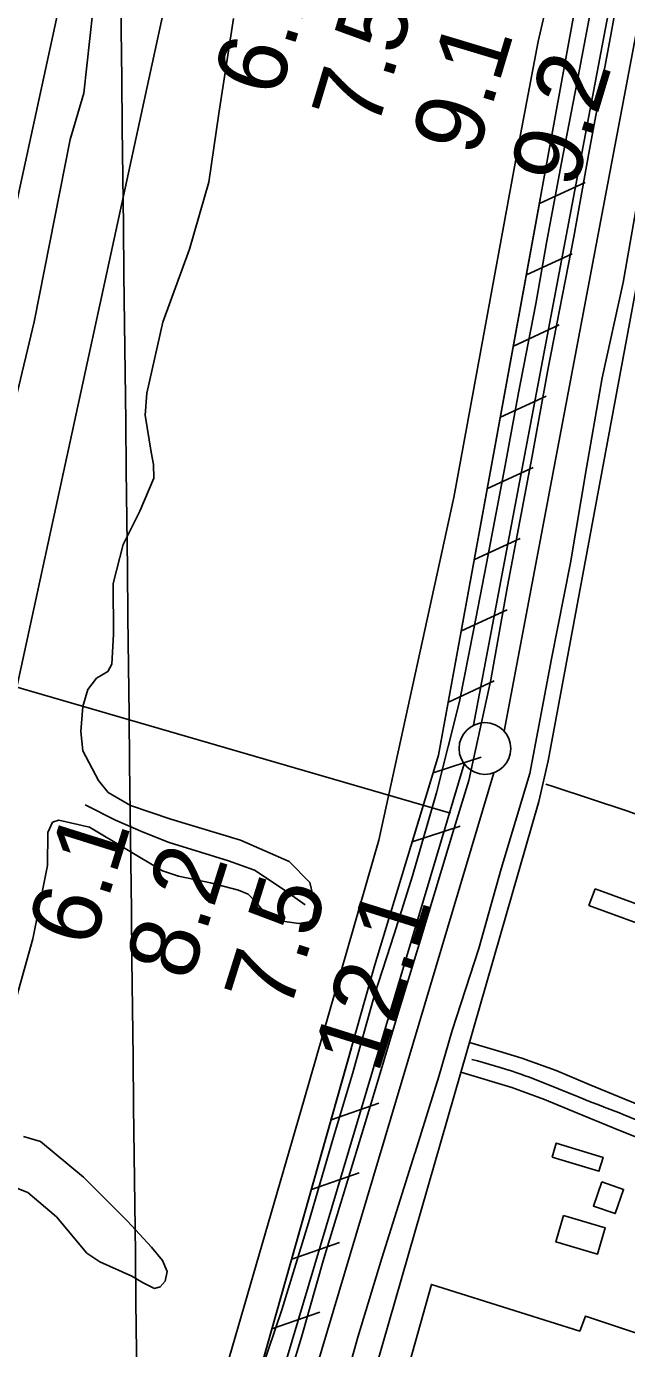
# Model space of a CAD drawing. Extents: x 3683613 to 3738215, y 469626 to 495384.
# Drawn here: x 3703578 to 3704159, y 477641 to 478919 of the extents above; entities that cross this region are included whole.
import ezdxf

# ---------------------------------------------------------------- set-up
doc = ezdxf.new("R2010")
doc.units = 0
for name, color, linetype in [('V-BLDG-OTLN', 7, 'Continuous'), ('V-DTCH-CNTR', 7, 'Continuous'), ('V-FLOD-BASE', 7, 'Continuous'), ('V-GRID-MAJR', 7, 'Continuous'), ('V-LEVE-TOET', 7, 'Continuous'), ('V-RIVR-EDGE', 7, 'Continuous'), ('V-RIVR-RANG', 7, 'Continuous'), ('V-ROAD-CNTR', 7, 'Continuous'), ('V-RRAP-FSHR', 7, 'Continuous'), ('V-SITE-VEGE', 7, 'Continuous'), ('V-SURV-LINE', 7, 'Continuous'), ('V-TOPO-DPTH', 7, 'Continuous'), ('V-TOPO-MINR', 7, 'Continuous'), ('V-TOPO-SHOR', 7, 'Continuous'), ('V-TOPO-WATR', 7, 'Continuous'), ('V-UTIL-LINE', 7, 'Continuous')]:
    doc.layers.add(name, color=color, linetype=linetype)

msp = doc.modelspace()

# ---------------------------------------------------------------- linework, layer by layer
at = {"layer": 'V-BLDG-OTLN'}
for points in [[(3704128.036, 478085.16000000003), (3704198.686, 478059.238), (3704192.823, 478043.25200000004), (3704122.171, 478069.173)], [(3704086.46, 477825.748), (3704090.546, 477839.179), (3704135.8310000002, 477825.4), (3704131.745, 477811.971)], [(3704134.612, 477801.68200000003), (3704155.713, 477794.393), (3704147.666, 477771.107), (3704126.568, 477778.396)], [(3704097.531, 477769.104), (3704137.957, 477757.433), (3704130.598, 477731.943), (3704090.173, 477743.615)]]:
    msp.add_lwpolyline(points, close=True, dxfattribs=at)
at = {"layer": 'V-DTCH-CNTR'}
for points in [[(3704299.161, 478107.469), (3704284.45, 478114.411), (3704159.711, 478160.291), (3704088.649, 478183.873), (3704080.5470000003, 478186.231)], [(3703940.634, 477598.05700000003), (3703969.83, 477702.53), (3704113.213, 477657.507), (3704118.744, 477671.767), (3704256.286, 477626.183)]]:
    msp.add_lwpolyline(points, dxfattribs=at)
at = {"layer": 'V-FLOD-BASE'}
msp.add_lwpolyline([(3704179.48, 479105.43700000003), (3704158.007, 478991.054), (3704143.785, 478912.54000000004), (3704122.216, 478796.748), (3704107.409, 478715.788), (3704082.765, 478588.667), (3704067.159, 478503.466), (3704043.253, 478377.768), (3704027.379, 478287.443), (3704005.91, 478189.825), (3703991.848, 478143.821), (3703959.222, 478035.969), (3703936.941, 477962.902), (3703911.352, 477877.732), (3703884.566, 477788.954), (3703865.73, 477727.612), (3703844.157, 477651.621), (3703814.27, 477552.788)], dxfattribs=at)
at = {"layer": 'V-GRID-MAJR'}
msp.add_spline([(3703712.5700000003, 475224.829), (3703642.089, 481281.841), (3703571.5670000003, 487342.321), (3703501.045, 493402.81200000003), (3703501.005, 493406.26900000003)], degree=3, dxfattribs=at)
at = {"layer": 'V-LEVE-TOET'}
for points in [[(3704167.595, 479178.552), (3704155.1350000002, 479106.82300000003), (3704142.522, 479036.837), (3704127.704, 478956.211), (3704110.899, 478865.651), (3704095.365, 478785.822), (3704081.258, 478709.867)], [(3704173.131, 478772.83900000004), (3704155.404, 478671.666), (3704135.034, 478579.27900000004), (3704119.889, 478492.476), (3704104.396, 478400.548), (3704085.899, 478307.737), (3704064.901, 478196.716), (3704037.193, 478104.628), (3704015.665, 478027.457), (3703989.876, 477948.212)], [(3704081.258, 478709.867), (3704070.838, 478650.867), (3704053.931, 478564.84), (3704041.09, 478494.5), (3704022.98, 478399.952), (3704010.366, 478335.085), (3703996.79, 478266.473), (3703974.703, 478178.004), (3703951.38, 478097.882), (3703933.81, 478041.16500000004), (3703915.095, 477983.608), (3703893.344, 477906.083), (3703874.94, 477845.042), (3703850.7490000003, 477762.108), (3703825.074, 477677.981), (3703798.679, 477599.884), (3703771.105, 477506.985), (3703750.997, 477439.04000000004), (3703724.04, 477344.642), (3703697.213, 477249.664), (3703669.512, 477152.107), (3703639.728, 477038.56), (3703627.069, 476980.907), (3703612.356, 476921.78500000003)], [(3703989.876, 477948.212), (3703976.92, 477903.701), (3703954.028, 477830.223), (3703953.694, 477829.516), (3703921.661, 477728.021), (3703898.488, 477651.512), (3703875.35, 477568.37), (3703845.859, 477462.511), (3703816.904, 477368.88), (3703788.816, 477278.18), (3703756.386, 477168.53), (3703730.927, 477064.506), (3703713.058, 476984.974), (3703701.682, 476943.381)]]:
    msp.add_lwpolyline(points, dxfattribs=at)
at = {"layer": 'V-RIVR-EDGE'}
msp.add_lwpolyline([(3703321.3665150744, 477624.2934469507), (3703330.4411275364, 477652.48635977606), (3703338.318062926, 477681.8828873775), (3703363.724602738, 477759.8625265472), (3703401.8700386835, 477891.23973639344), (3703437.577072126, 478007.6148098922), (3703453.9980650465, 478093.4209139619), (3703484.288831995, 478204.40644063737), (3703511.560171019, 478308.1955138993), (3703538.2549378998, 478421.59123897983), (3703567.407404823, 478557.7932989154), (3703585.6041313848, 478633.389459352), (3703620.258961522, 478809.7997979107), (3703633.577398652, 478854.7913626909), (3703642.1778643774, 478934.01321171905), (3703659.1576163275, 479003.00878842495), (3703684.6650971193, 479121.8103890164), (3703704.16192616, 479237.62521906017), (3703733.9295603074, 479379.82902418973), (3703760.087834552, 479519.04012106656), (3703797.7799057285, 479709.85078858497), (3703822.0793184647, 479825.6537432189)], dxfattribs=at)
at = {"layer": 'V-ROAD-CNTR'}
for points in [[(3703726.55050797, 476963.34804728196), (3703726.55050797, 476963.34804728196), (3704073.5738139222, 478169.58763479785), (3704082.870795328, 478208.9135561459), (3704324.341312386, 479507.44095908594), (3704404.9751511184, 479907.30515935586), (3704509.589941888, 480585.20680355)], [(3704006.546947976, 477936.6061007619), (3704034.9398911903, 477928.1241177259), (3704057.092846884, 477921.50713096), (3704090.301780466, 477909.30715536), (3704122.4497161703, 477895.78318240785), (3704157.01964703, 477881.80221036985), (3704191.8445773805, 477867.6362387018), (3704211.50453806, 477859.0012559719), (3704232.220496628, 477854.7082645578), (3704255.771449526, 477848.5402768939), (3704283.152394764, 477833.49030699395), (3704308.905343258, 477819.33533530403)], [(3703998.2529645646, 477907.776158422), (3704047.616865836, 477893.0271879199), (3704079.307802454, 477881.38521120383), (3704111.00973905, 477868.04923787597), (3704145.7436695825, 477854.00226597), (3704180.158600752, 477840.00229396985), (3704202.328556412, 477830.2653134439), (3704225.372510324, 477825.490322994), (3704244.5774719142, 477820.46033305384), (3704268.7024236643, 477807.2003595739), (3704294.455372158, 477793.0453878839)]]:
    msp.add_lwpolyline(points, dxfattribs=at)
msp.add_spline([(3704008.9379431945, 477920.2371334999), (3704052.3548563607, 477907.2671594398), (3704116.72972761, 477881.9162101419), (3704186.001589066, 477853.819266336), (3704206.916547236, 477844.633284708), (3704250.1744607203, 477834.50030497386), (3704301.680357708, 477806.19036159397)], degree=3, dxfattribs=at)
at = {"layer": 'V-RRAP-FSHR'}
for p, q in [((3704074.18, 478747.86600000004), (3704118.56, 478768.234)), ((3704061.6070000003, 478679.005), (3704105.987, 478699.373)), ((3704049.034, 478610.143), (3704093.414, 478630.511)), ((3704036.461, 478541.282), (3704080.841, 478561.65)), ((3704023.8880000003, 478472.42), (3704068.268, 478492.788)), ((3704011.315, 478403.558), (3704055.6950000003, 478423.92600000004)), ((3703998.742, 478334.697), (3704043.122, 478355.065)), ((3703986.169, 478265.835), (3704030.549, 478286.20300000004)), ((3703971.633, 478197.45), (3704018.051, 478212.609)), ((3703951.268, 478130.478), (3703997.686, 478145.637)), ((3703872.728, 477861.732), (3703918.841, 477877.79600000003)), ((3703853.676, 477794.375), (3703899.789, 477810.438)), ((3703834.6240000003, 477727.017), (3703880.737, 477743.081)), ((3703815.572, 477659.66000000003), (3703861.685, 477675.724))]:
    msp.add_line(p, q, dxfattribs=at)
for points in [[(3702858.024, 475214.887), (3703006.626, 475446.686), (3703077.99, 475579.17), (3703285.585, 476047.11), (3703546.844, 476749.722), (3703611.737, 476939.011), (3703915.1010000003, 478011.539), (3703976.764, 478214.324), (3704202.289, 479449.512), (3704357.755, 480250.503), (3704382.901, 480399.208)], [(3704074.884, 478751.72000000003), (3703976.764, 478214.324), (3703949.967, 478126.2)], [(3703892.432, 477931.393), (3703679.125, 477177.257)]]:
    msp.add_lwpolyline(points, dxfattribs=at)
at = {"layer": 'V-SITE-VEGE'}
for p, q in [((3704121.73, 479112.25), (3704072.927, 478904.72000000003)), ((3703764.109, 478834.875), (3703778.3510000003, 478926.775)), ((3704072.927, 478904.72000000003), (3704053.772, 478802.73600000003)), ((3703754.426, 478768.469), (3703764.109, 478834.875)), ((3704053.772, 478802.73600000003), (3703991.316, 478463.729)), ((3703735.644, 478703.666), (3703754.426, 478768.469)), ((3703710.031, 478633.27), (3703735.644, 478703.666)), ((3703694.356, 478564.61099999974), (3703710.031, 478633.27)), ((3703693.0270000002, 478543.123), (3703694.356, 478564.61099999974)), ((3703698.667, 478507.586), (3703693.0270000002, 478543.123)), ((3703701.055, 478495.55), (3703698.667, 478507.586)), ((3703701.3540000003, 478482.261), (3703701.055, 478495.55)), ((3703687.8680000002, 478450.521), (3703701.3540000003, 478482.261)), ((3703991.316, 478463.729), (3703919.0130000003, 478132.354)), ((3703671.674, 478418.12), (3703687.8680000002, 478450.521)), ((3703661.946, 478380.422), (3703671.674, 478418.12)), ((3703662.153, 478331.162), (3703661.946, 478380.422)), ((3703660.6890000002, 478302.4179999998), (3703662.153, 478331.162)), ((3703656.918, 478295.38300000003), (3703660.6890000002, 478302.4179999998)), ((3703637.362, 478278.014), (3703645.884, 478288.78399999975)), ((3703645.884, 478288.78399999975), (3703656.918, 478295.38300000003)), ((3703632.596, 478261.5849999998), (3703637.362, 478278.014)), ((3703630.727, 478237.3629999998), (3703632.596, 478261.5849999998)), ((3703632.66, 478218.669), (3703630.727, 478237.3629999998)), ((3703647.815, 478189.99700000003), (3703632.66, 478218.669)), ((3703657.144, 478178.42), (3703647.815, 478189.99700000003)), ((3703678.59, 478165.605), (3703657.144, 478178.42)), ((3703717.572, 478152.58400000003), (3703678.59, 478165.605)), ((3703598.782, 478139.624), (3703603.39, 478149.70300000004)), ((3703603.39, 478149.70300000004), (3703609.3910000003, 478151.65)), ((3703609.3910000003, 478151.65), (3703639.166, 478144.76900000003)), ((3703639.166, 478144.76900000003), (3703709.634, 478102.53500000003)), ((3703785.123, 478132.35000000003), (3703717.572, 478152.58400000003)), ((3703598.299, 478107.575), (3703598.782, 478139.624)), ((3703832.1350000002, 478111.65299999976), (3703785.123, 478132.35000000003)), ((3703919.0130000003, 478132.354), (3703846.711, 477881.376)), ((3703584.18, 478036.835), (3703598.299, 478107.575)), ((3703852.242, 478091.253), (3703832.1350000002, 478111.65299999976)), ((3703709.634, 478102.53500000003), (3703725.164, 478097.44800000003)), ((3703725.164, 478097.44800000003), (3703756.14, 478090.892)), ((3703756.14, 478090.892), (3703783.196, 478083.949)), ((3703783.196, 478083.949), (3703792.656, 478079.931)), ((3703792.656, 478079.931), (3703800.082, 478072.24100000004)), ((3703857.272, 478069.302), (3703852.242, 478091.253)), ((3703800.082, 478072.24100000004), (3703808.472, 478062.157)), ((3703855.128, 478057.166), (3703857.272, 478069.302)), ((3703808.472, 478062.157), (3703825.889, 478053.7849999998)), ((3703851.29, 478053.148), (3703855.128, 478057.166)), ((3703825.889, 478053.7849999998), (3703841.65, 478051.7219999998)), ((3703841.65, 478051.7219999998), (3703851.29, 478053.14799999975)), ((3703557.056, 477939.809), (3703584.18, 478036.835)), ((3703846.711, 477881.376), (3703741.822, 477520.856)), ((3703591.632, 477840.854), (3703575.203, 477845.61999999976)), ((3703633.213, 477806.43099999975), (3703591.632, 477840.854)), ((3703560.548, 477798.745), (3703579.453, 477791.313)), ((3703675.883, 477763.874), (3703633.213, 477806.43099999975)), ((3703579.453, 477791.313), (3703607.181, 477768.066)), ((3703607.181, 477768.066), (3703636.387, 477732.75800000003)), ((3703699.12, 477738.71), (3703675.883, 477763.874)), ((3703709.6890000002, 477725.6499999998), (3703699.12, 477738.71)), ((3703636.387, 477732.75800000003), (3703648.972, 477724.278)), ((3703648.972, 477724.278), (3703680.112, 477710.472)), ((3703714.1580000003, 477715.1719999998), (3703709.6890000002, 477725.6499999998)), ((3703680.112, 477710.472), (3703690.835, 477704.066)), ((3703712.255, 477705.7599999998), (3703714.1580000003, 477715.1719999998)), ((3703690.835, 477704.066), (3703701.839, 477698.57300000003)), ((3703701.839, 477698.57300000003), (3703707.244, 477700.20500000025)), ((3703707.244, 477700.205), (3703712.255, 477705.7599999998))]:
    msp.add_line(p, q, dxfattribs=at)
at = {"layer": 'V-SURV-LINE'}
for points in [[(3704010.553824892, 478243.30529999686), (3704341.9905368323, 479993.6624916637)], [(3704371.4651746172, 479988.0726974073), (3704040.0286145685, 478237.71630789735)], [(3703717.96600561, 477255.97462205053), (3704001.4893040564, 478206.03379666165)], [(3704030.2309531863, 478197.4362398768), (3703746.707644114, 477247.3770296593)]]:
    msp.add_lwpolyline(points, dxfattribs=at)
msp.add_circle((3704021.57537, 478220.88503), 25, dxfattribs=at)
at = {"layer": 'V-TOPO-DPTH'}
msp.add_lwpolyline([(3703263.13, 477205.23), (3703539.2, 478145.27), (3703717.7600000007, 478966.58), (3703818.3847297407, 479545.8457634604), (3703829.64005972, 479610.71979419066), (3703840.8772792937, 479675.596957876), (3703852.087333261, 479740.4788209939)], dxfattribs=at)
at = {"layer": 'V-TOPO-MINR'}
msp.add_lwpolyline([(3703171.28330504, 477279.5307196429), (3703443.73, 478175.02), (3703621.93, 478995.16000000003), (3703804.2594584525, 479878.9320556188), (3703806.8902744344, 479891.5825986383), (3703809.547795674, 479904.22748493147), (3703812.2453747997, 479916.8638861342), (3703814.969659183, 479929.49463061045), (3703819.391093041, 479949.83750935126), (3703819.928210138, 479952.2917890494), (3703820.47002079, 479954.7450250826), (3703821.0188717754, 479957.1966956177), (3703821.572416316, 479959.6473224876), (3703944.755714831, 480501.3794367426), (3703957.18351741, 480556.01299338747), (3703969.61739966, 480610.6451658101), (3703982.0604014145, 480665.27526189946), (3703994.5094828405, 480719.90397376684), (3704012.408822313, 480798.41910537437)], dxfattribs=at)
at = {"layer": 'V-TOPO-SHOR'}
msp.add_lwpolyline([(3703847.528, 478069.542), (3703825.473, 478085.447), (3703798.611, 478103.358), (3703773.542, 478112.316), (3703746.367, 478120.697), (3703715.9930000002, 478130.064), (3703690.899, 478140.079), (3703664.181, 478151.646), (3703634.747, 478166.324)], dxfattribs=at)
at = {"layer": 'V-TOPO-WATR'}
msp.add_lwpolyline([(3703263.13, 477205.23), (3703539.2, 478145.27), (3703717.7600000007, 478966.58), (3703818.3847297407, 479545.8457634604), (3703829.64005972, 479610.71979419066), (3703840.8772792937, 479675.596957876), (3703852.087333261, 479740.4788209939)], dxfattribs=at)
at = {"layer": 'V-UTIL-LINE'}
msp.add_lwpolyline([(3703988.1410000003, 478158.438), (3701413.6890000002, 478906.251)], dxfattribs=at)

# ---------------------------------------------------------------- texts
at = {"layer": 'V-RIVR-RANG'}
for s, rotation, p in [('6.1', 73.24832571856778, (3703821.7136466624, 478848.77305525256)), ('7.5', 73.24832571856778, (3703916.858397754, 478817.9187857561)), ('9.1', 73.24832571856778, (3704013.3706466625, 478791.61105525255)), ('9.2', 73.24832571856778, (3704108.5153977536, 478760.7567857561)), ('6.1', 72.54832571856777, (3703641.7060398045, 478026.1983938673)), ('8.2', 72.54832571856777, (3703736.4650694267, 477994.1796534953)), ('7.5', 72.54832571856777, (3703831.9360694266, 477964.42665349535)), ('12.1', 72.54832571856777, (3703918.1514545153, 477905.23102865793))]:
    msp.add_text(s, height=66.99999999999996, rotation=rotation, dxfattribs=at).set_placement(p)

doc.saveas('drawing.dxf')
